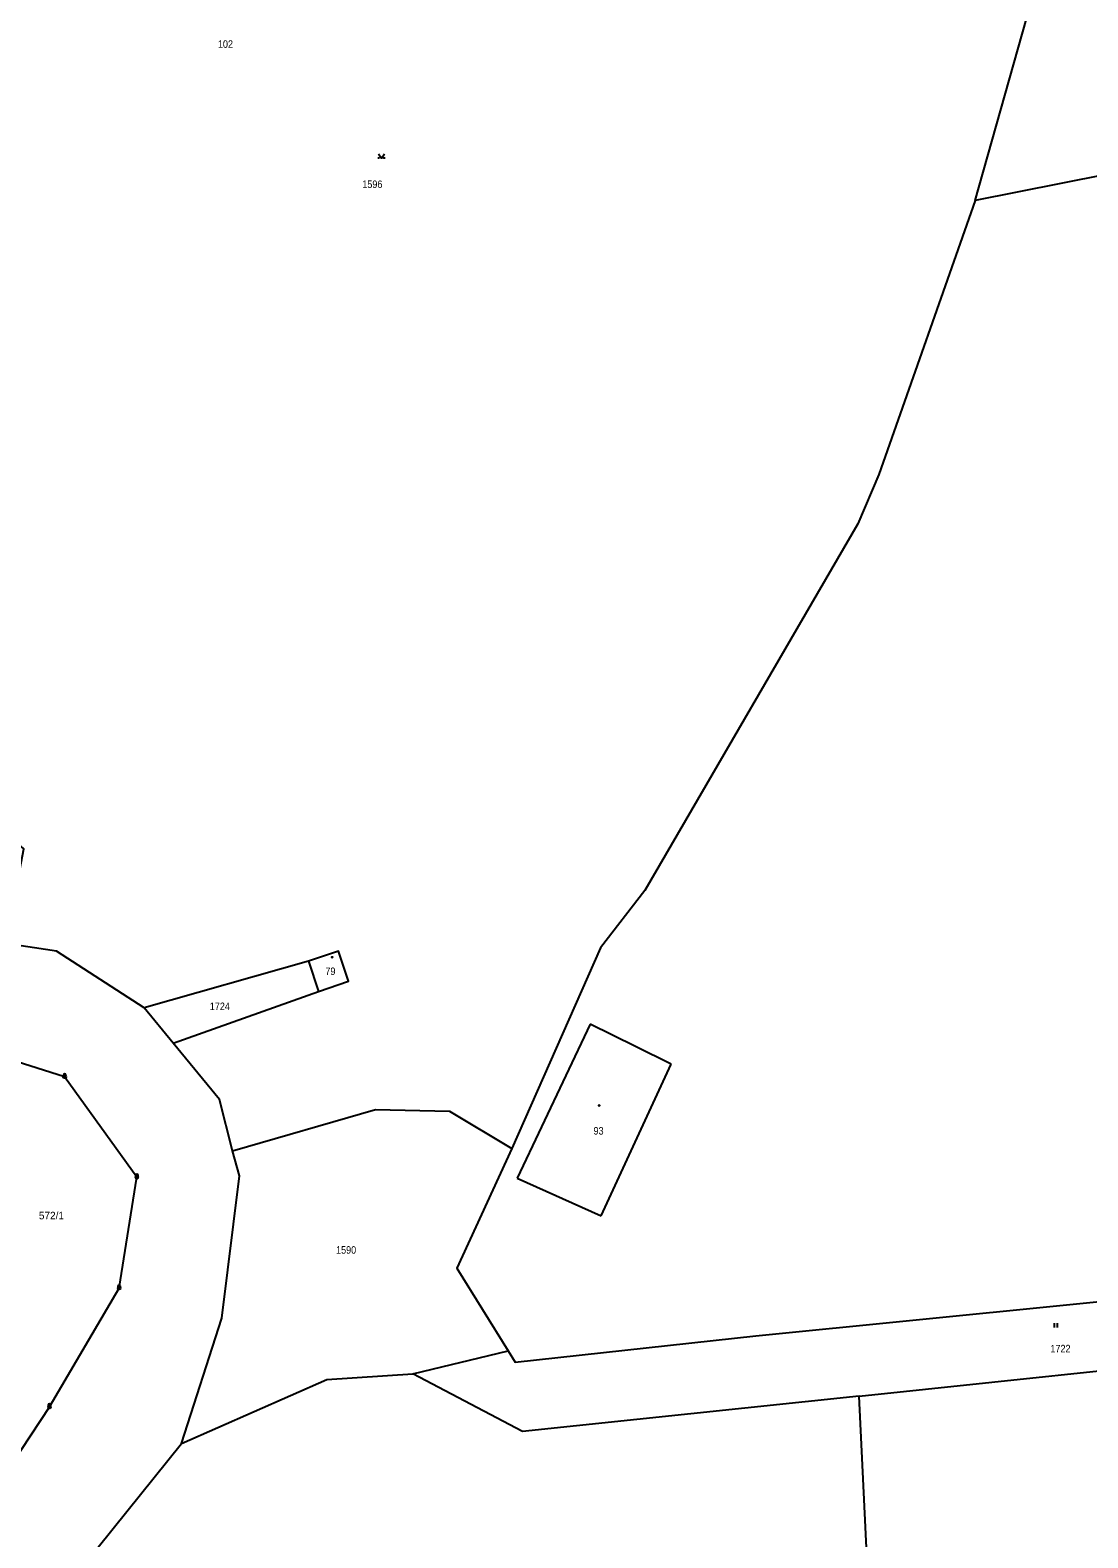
# Model space of a CAD drawing. Extents: x -873052 to -871788, y -1075760 to -1074911.
# Drawn here: x -872893.4 to -872787.8, y -1075410.5 to -1075259.8 of the extents above; entities that cross this region are included whole.
import ezdxf
from ezdxf.enums import TextEntityAlignment as Align

# ---------------------------------------------------------------- set-up
doc = ezdxf.new("R2010")
doc.units = 0
doc.header["$LTSCALE"] = 0.3
for name, color, linetype, lineweight in [('1', 7, 'Continuous', 25), ('16', 7, 'Continuous', 25), ('24', 7, 'Continuous', 25), ('25', 7, 'Continuous', 25)]:
    doc.layers.add(name, color=color, linetype=linetype, lineweight=lineweight)
doc.layers.add('18', color=7, linetype='Continuous')
doc.layers.add('19', color=7, linetype='Continuous')

msp = doc.modelspace()

# ---------------------------------------------------------------- linework, layer by layer
at = {"layer": '1'}
for p, q in [((-872865.66, -1075352.85), (-872864.65, -1075355.86)), ((-872879.17, -1075361.02), (-872882.06, -1075357.49)), ((-872837.52, -1075359.13), (-872844.8, -1075374.51)), ((-872833, -1075361.37), (-872837.52, -1075359.13)), ((-872890, -1075364.39), (-872904.98, -1075359.67)), ((-872829.43, -1075363.13), (-872833, -1075361.37)), ((-872836.43, -1075378.29), (-872829.43, -1075363.13)), ((-872882.79, -1075374.43), (-872890, -1075364.39)), ((-872884.56, -1075385.51), (-872882.79, -1075374.43)), ((-872844.8, -1075374.51), (-872836.43, -1075378.29)), ((-872891.52, -1075397.38), (-872884.56, -1075385.51)), ((-872863.81, -1075394.63), (-872855.23, -1075394.06)), ((-872878.32, -1075401.04), (-872863.81, -1075394.63))]:
    msp.add_line(p, q, dxfattribs=at)
msp.add_lwpolyline([(-872733.84, -1075080.34), (-872730.29, -1075263.19), (-872799.07, -1075276.85), (-872780.16, -1075209.85), (-872781.81, -1075204.84), (-872834.07, -1075152.34), (-872861.32, -1075125.81), (-872883.58, -1075093.06), (-872889.98, -1075081.8)], close=True, dxfattribs=at)
for points in [[(-872873.24, -1075371.8), (-872874.52, -1075366.66), (-872879.17, -1075361.02), (-872864.65, -1075355.86), (-872861.65, -1075354.85), (-872862.66, -1075351.84), (-872865.66, -1075352.85), (-872882.06, -1075357.49), (-872890.82, -1075351.83), (-872895.87, -1075351.06), (-872894.06, -1075341.62), (-872907.18, -1075330.08), (-872921.93, -1075261.26)], [(-872799.07, -1075276.85), (-872808.68, -1075304.22), (-872810.8, -1075309.14), (-872832.07, -1075345.79), (-872836.5, -1075351.51), (-872845.33, -1075371.56)], [(-872874.29, -1075388.5), (-872872.54, -1075374.29), (-872873.24, -1075371.8), (-872858.97, -1075367.67), (-872851.55, -1075367.83), (-872845.33, -1075371.56)], [(-872845.33, -1075371.56), (-872850.83, -1075383.5), (-872845.71, -1075391.78)], [(-872808.66, -1075437.63), (-872810.64, -1075396.3), (-872771.55, -1075392.17), (-872725.26, -1075387.33), (-872576.3, -1075378.91), (-872564.93, -1075510.69)], [(-872810.64, -1075396.3), (-872844.26, -1075399.85), (-872855.23, -1075394.06), (-872845.71, -1075391.78), (-872845.02, -1075392.89), (-872820.97, -1075390.28), (-872773.95, -1075385.58)], [(-872892.11, -1075418.17), (-872878.32, -1075401.04), (-872874.29, -1075388.5)], [(-872891.52, -1075397.38), (-872894.35, -1075401.67), (-872895.25, -1075403.04)]]:
    msp.add_lwpolyline(points, dxfattribs=at)
at = {"layer": '24'}
for centre, radius in [((-872889.9995, -1075364.3895), 0.1505), ((-872889.9995, -1075364.3895), 0.00652), ((-872882.7895, -1075374.4295), 0.1505), ((-872882.7895, -1075374.4295), 0.00652), ((-872884.5595, -1075385.5095), 0.1505), ((-872884.5595, -1075385.5095), 0.00652), ((-872891.5195, -1075397.3795), 0.1505), ((-872891.5195, -1075397.3795), 0.00652)]:
    msp.add_circle(centre, radius, dxfattribs=at)
for centre in [(-872889.9996, -1075364.2201), (-872882.7896, -1075374.2601), (-872884.5596, -1075385.3401), (-872891.5196, -1075397.2101)]:
    msp.add_arc(centre, 0.1311, 328.53402, 210.28963, dxfattribs=at)
at = {"layer": '25'}
for p, q in [((-872791.145, -1075389.459), (-872791.145, -1075389.009)), ((-872790.834, -1075389.459), (-872790.834, -1075389.009))]:
    msp.add_line(p, q, dxfattribs=at)
msp.add_lwpolyline([(-872858.66, -1075272.169), (-872858.36, -1075272.62), (-872858.059, -1075272.169)], dxfattribs=at)
for centre, radius in [((-872858.63, -1075272.59), 0.03), ((-872858.089, -1075272.59), 0.03), ((-872863.2795, -1075352.4495), 0.0525), ((-872836.6295, -1075367.2595), 0.0525)]:
    msp.add_circle(centre, radius, dxfattribs=at)

# ---------------------------------------------------------------- texts
at = {"layer": '16', "width": 0.9}
msp.add_text('102', height=0.75, dxfattribs=at).set_placement((-872873.9395, -1075261.58), align=Align.CENTER)
at = {"layer": '18', "width": 0.9}
for s, p in [('1596', (-872859.2695, -1075275.585)), ('1724', (-872874.4995, -1075357.725)), ('1590', (-872861.8895, -1075382.065)), ('1722', (-872790.5495, -1075391.925))]:
    msp.add_text(s, height=0.75, dxfattribs=at).set_placement(p, align=Align.CENTER)
at = {"layer": '18'}
msp.add_text('572/1', height=0.75, dxfattribs=at).set_placement((-872891.3195, -1075378.63), align=Align.CENTER)
at = {"layer": '19', "width": 0.9}
for s, p in [('79', (-872863.4595, -1075354.225)), ('93', (-872836.6795, -1075370.165))]:
    msp.add_text(s, height=0.75, dxfattribs=at).set_placement(p, align=Align.CENTER)

doc.saveas('drawing.dxf')
